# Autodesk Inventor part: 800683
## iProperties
Created: 2007-10
Part Number: 800683
Document SubType Name: Modeling
Designer: JJ
Density: 7.86 g/cm^3
Mass: 20.0028 g
Surface Area: 15.6834 cm^2
Volume: 2.54489 cm^3
Material: Steel, Mild
Description: DR342 M12 X 14
Component Category: Fasteners
Author: JJ
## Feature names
1. Extrusion1
2. Extrusion2
3. Extrusion3
4. Extrusion4
5. Extrusion5
6. Fillet1
7. Extrusion6
8. Fillet2
9. Chamfer2
10. Chamfer3
11. Chamfer4
12. Chamfer5
13. Chamfer6
14. Chamfer7
15. Chamfer8
16. Chamfer9
17. Chamfer10
